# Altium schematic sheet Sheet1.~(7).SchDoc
size A4; SheetNumber: 1; SheetTotal: 1
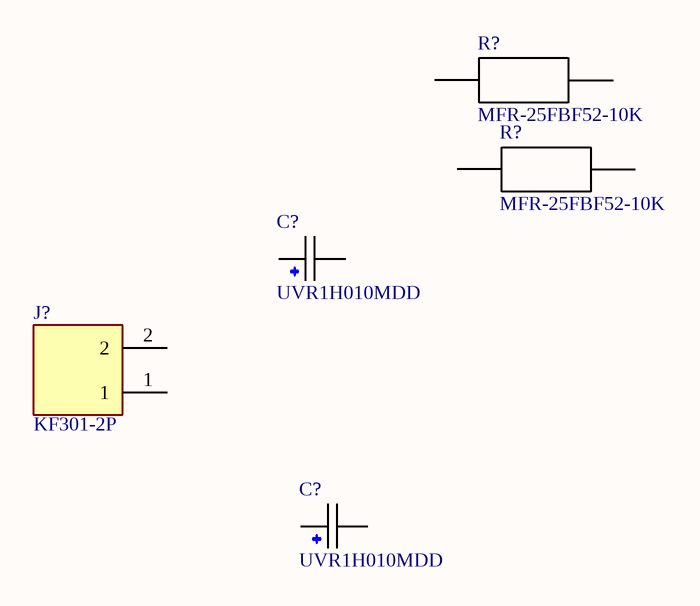
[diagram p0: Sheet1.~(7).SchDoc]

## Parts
(Parts that share a designator on the sheet are numbered #1, #2 ... from top to bottom, then left to right.)
C?#1  UVR1H010MDD  [CAPPRD200W50D550H1250]
C?#2  UVR1H010MDD  [CAPPRD200W50D550H1250]
J?  KF301-2P  [HANDSON_KF301-2P]
R?#1  MFR-25FBF52-10K  [RESAD1100W55L680D260]
R?#2  MFR-25FBF52-10K  [RESAD1100W55L680D260]

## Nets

Not connected (* = marked no-connect by the designer): C?#1 1 2; C?#2 1 2; J? 1 2; R?#1 1 2; R?#2 1 2

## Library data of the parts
C?#1 C?#2 = UVR1H010MDD: 1 ÂµF 50 V Aluminum Electrolytic Capacitors Radial, Can - 2000 Hrs @ 85Â°C; MF: Nichicon
J? = KF301-2P: 2 Pin Terminal Block 5mm Pitch; MF: Handson Technology
R?#1 R?#2 = MFR-25FBF52-10K: 10.2 kOhms Â±1% 0.25W, 1/4W Through Hole Resistor Axial - Metal Film; MF: Yageo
